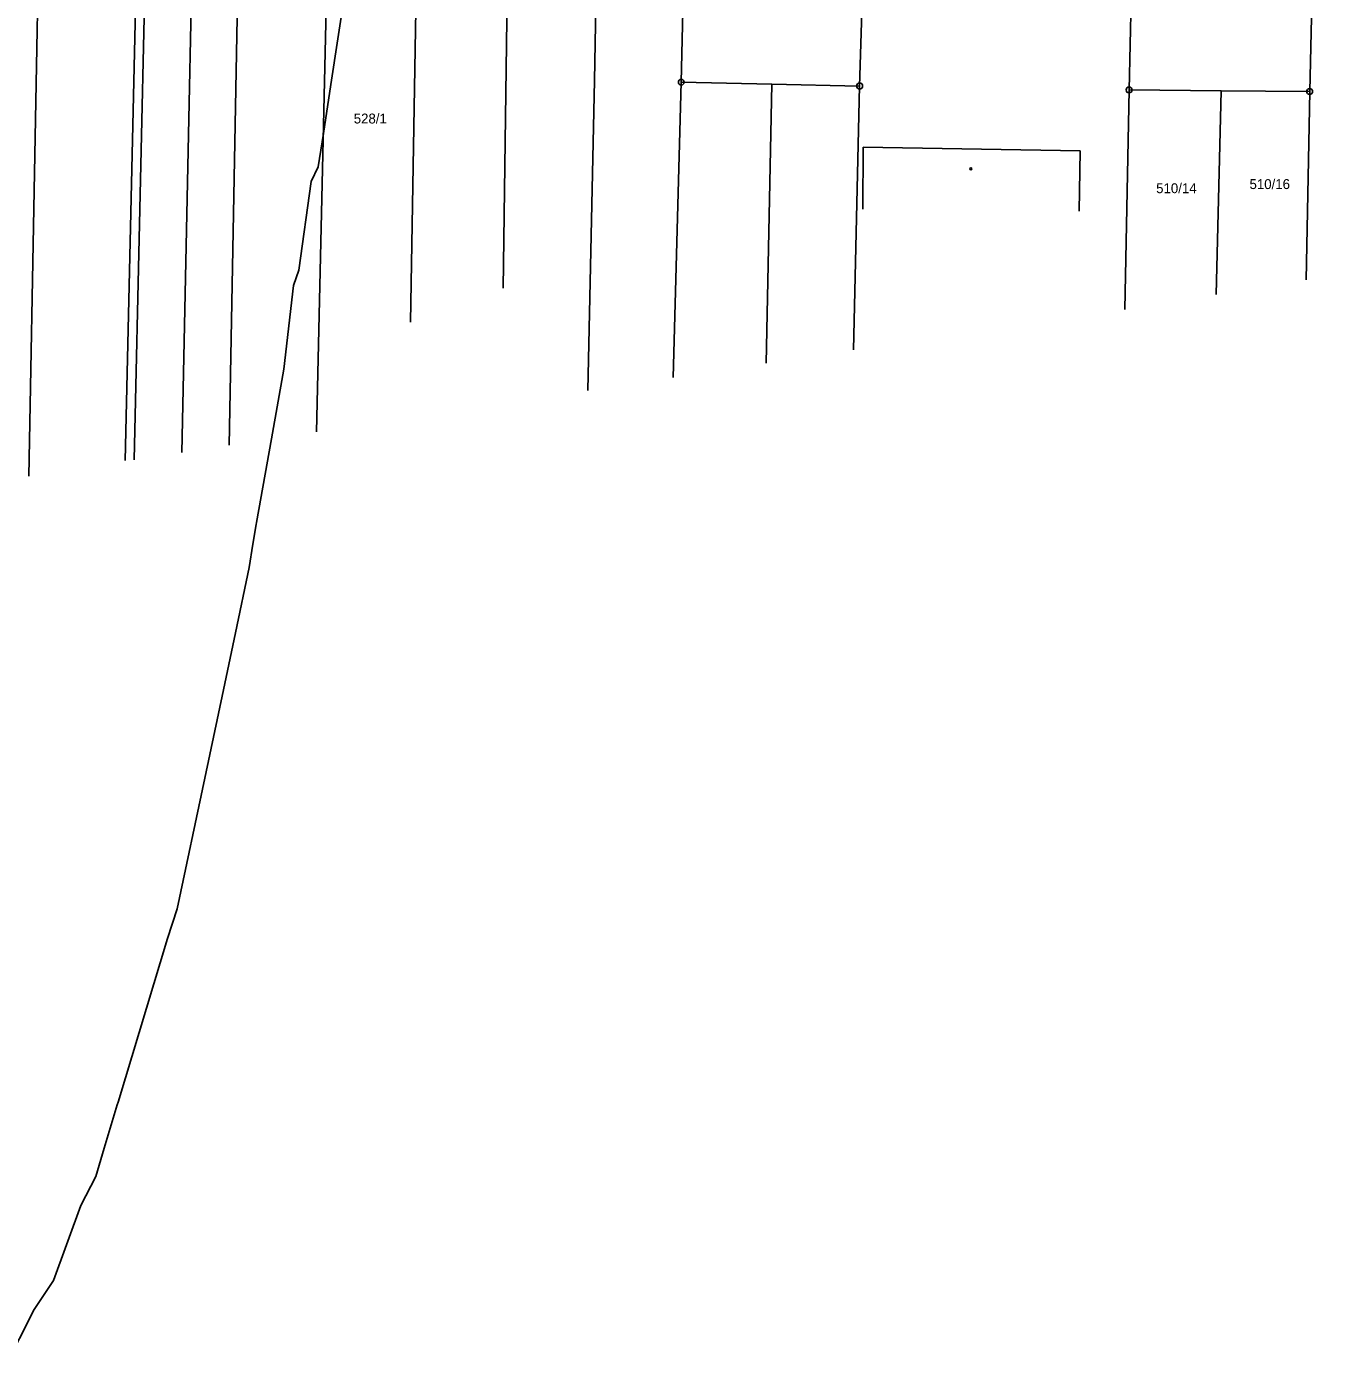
# Model space of a CAD drawing. Extents: x -747333 to -745433, y -1133152 to -1130600.
# Drawn here: x -746635.6 to -746412.9, y -1132831.3 to -1132600.8 of the extents above; entities that cross this region are included whole.
import ezdxf

# ---------------------------------------------------------------- set-up
doc = ezdxf.new("R2010")
doc.units = 0
for name, color, linetype in [('Vrstva 1', 7, 'Continuous'), ('Vrstva 18', 7, 'Continuous'), ('Vrstva 24', 7, 'Continuous'), ('Vrstva 25', 7, 'Continuous'), ('Vrstva 3', 7, 'Continuous'), ('Vrstva 37', 7, 'Continuous'), ('Vrstva 52', 7, 'Continuous'), ('Vrstva 6', 7, 'Continuous')]:
    doc.layers.add(name, color=color, linetype=linetype)

msp = doc.modelspace()

# ---------------------------------------------------------------- linework, layer by layer
at = {"layer": 'Vrstva 1'}
for points in [[(-746520.49, -1132500.34), (-746523.05, -1132610.33)], [(-746617.07, -1132675.21), (-746613.21, -1132502.87)], [(-746415.02, -1132611.93), (-746412.87, -1132517.7)], [(-746615.66, -1132545), (-746618.65, -1132675.35)], [(-746492.38, -1132610.98), (-746491.44, -1132579.84)], [(-746446.07, -1132611.66), (-746445.35, -1132580.44)], [(-746507.48, -1132610.66), (-746523.05, -1132610.33)], [(-746492.38, -1132610.98), (-746507.48, -1132610.66)], [(-746493.45, -1132656.34), (-746492.38, -1132610.98)], [(-746446.07, -1132611.66), (-746446.82, -1132649.4)], [(-746430.26, -1132611.8), (-746446.07, -1132611.66)], [(-746415.02, -1132611.93), (-746430.26, -1132611.8)], [(-746491.83, -1132632.12), (-746491.75, -1132621.52)], [(-746491.75, -1132621.52), (-746454.48, -1132622.1)], [(-746454.48, -1132622.1), (-746454.62, -1132632.47)]]:
    msp.add_lwpolyline(points, dxfattribs=at)
at = {"layer": 'Vrstva 24'}
for p, q in [((-746523.1, -1132610.33), (-746523, -1132610.33)), ((-746492.43, -1132610.98), (-746492.33, -1132610.98)), ((-746446.12, -1132611.66), (-746446.02, -1132611.66)), ((-746415.07, -1132611.93), (-746414.97, -1132611.93))]:
    msp.add_line(p, q, dxfattribs=at)
for centre in [(-746523.05, -1132610.33), (-746492.38, -1132610.98), (-746446.07, -1132611.66), (-746415.02, -1132611.93)]:
    msp.add_circle(centre, 0.499289, dxfattribs=at)
at = {"layer": 'Vrstva 25'}
msp.add_circle((-746473.27, -1132625.23), 0.174503, dxfattribs=at)
at = {"layer": 'Vrstva 3'}
for points in [[(-746491.83, -1132632.12), (-746491.75, -1132621.52)], [(-746491.75, -1132621.52), (-746454.48, -1132622.1)], [(-746454.48, -1132622.1), (-746454.62, -1132632.47)]]:
    msp.add_lwpolyline(points, dxfattribs=at)
at = {"layer": 'Vrstva 37'}
msp.add_circle((-746473.27, -1132625.23), 0.174503, dxfattribs=at)
at = {"layer": 'Vrstva 52'}
msp.add_lwpolyline([(-746580.75, -1132594.25), (-746583.31, -1132610.75), (-746584.57, -1132619.15), (-746585.44, -1132624.88), (-746586.69, -1132627.37), (-746588.81, -1132642.62), (-746589.69, -1132645.25), (-746591.37, -1132659.62), (-746593.51, -1132671.61), (-746596.06, -1132686), (-746596.12, -1132686.33), (-746596.67, -1132689.74), (-746597.31, -1132693.75), (-746599.67, -1132704.94), (-746601.74, -1132714.73), (-746604.95, -1132729.92), (-746609.69, -1132752.37), (-746611.37, -1132757.5), (-746619.87, -1132785.62), (-746620.01, -1132786.06), (-746622.24, -1132793.55), (-746623.69, -1132798.37), (-746626.25, -1132803.38), (-746630.94, -1132816.25), (-746634.31, -1132821.25), (-746639.36, -1132831.34)], dxfattribs=at)
at = {"layer": 'Vrstva 6'}
for points in [[(-746537.98, -1132610.05), (-746535.13, -1132453.3)], [(-746606.11, -1132540.09), (-746608.92, -1132673.97)], [(-746582.99, -1132549.96), (-746585.75, -1132670.43)], [(-746569.62, -1132651.54), (-746568.01, -1132557.67)], [(-746635.22, -1132678.03), (-746633.28, -1132573.72)], [(-746553.66, -1132645.75), (-746552.94, -1132591.21)], [(-746600.75, -1132672.72), (-746599.26, -1132593.08)], [(-746539.11, -1132663.31), (-746537.98, -1132610.05)], [(-746523.05, -1132610.33), (-746524.45, -1132661.07)], [(-746508.44, -1132658.63), (-746507.48, -1132610.66)], [(-746430.26, -1132611.8), (-746431.12, -1132646.84)], [(-746415.63, -1132644.31), (-746415.02, -1132611.93)]]:
    msp.add_lwpolyline(points, dxfattribs=at)

# ---------------------------------------------------------------- texts
at = {"layer": 'Vrstva 18'}
for s, p in [('528/1', (-746579.35, -1132617.42)), ('510/16', (-746425.36, -1132628.69)), ('510/14', (-746441.41, -1132629.4))]:
    msp.add_text(s, height=1.7, dxfattribs=at).set_placement(p)

doc.saveas('drawing.dxf')
